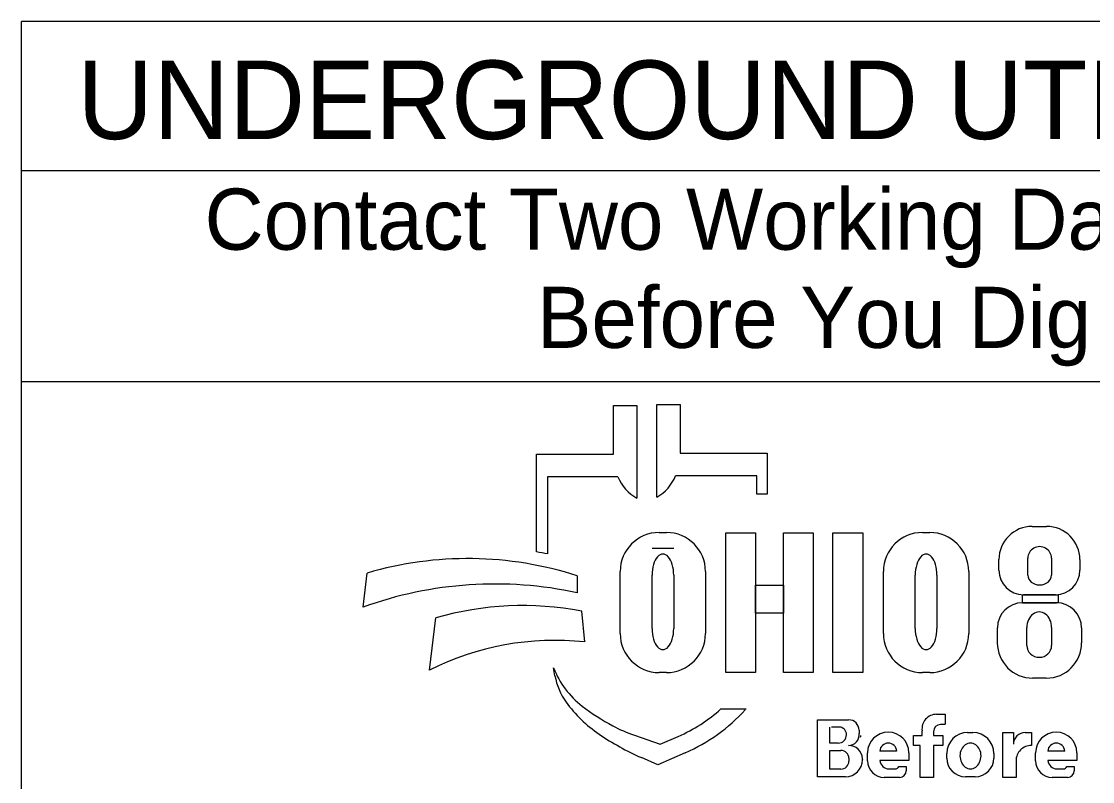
# Model space of a CAD drawing. Extents: x 0 to 2329303, y 0 to 694397.
# Drawn here: x 3 to 5.454, y 3.565 to 5.307 of the extents above; entities that cross this region are included whole.
import ezdxf

# ---------------------------------------------------------------- set-up
doc = ezdxf.new("R2010")
doc.units = 0
doc.layers.add('SH_Data', color=7, linetype='Continuous')

msp = doc.modelspace()

# ---------------------------------------------------------------- linework, layer by layer
at = {"layer": 'SH_Data'}
for p, q in [((3, 2.97), (3, 5.3075)), ((7.25, 5.3075), (3, 5.3075)), ((3, 4.9659), (7.25, 4.9659)), ((3, 4.4825), (7.25, 4.4825)), ((4.356, 4.3155), (4.356, 4.427)), ((4.356, 4.427), (4.4097, 4.427)), ((4.4097, 4.427), (4.4097, 4.2149)), ((4.4553, 4.2172), (4.4553, 4.4293)), ((4.4553, 4.4293), (4.509, 4.4293)), ((4.509, 4.4293), (4.509, 4.3178)), ((4.1801, 4.0916), (4.1801, 4.3155)), ((4.1801, 4.3155), (4.356, 4.3155)), ((4.509, 4.3178), (4.7082, 4.3178)), ((4.7082, 4.3178), (4.7082, 4.224)), ((4.2053, 4.264), (4.2053, 4.0872)), ((4.3664, 4.264), (4.2053, 4.264)), ((4.6849, 4.2664), (4.4986, 4.2664)), ((4.6849, 4.224), (4.6849, 4.2664)), ((4.7082, 4.224), (4.6849, 4.224)), ((5.3156, 4.1503), (5.3483, 4.1503)), ((4.461, 4.1363), (4.4776, 4.1363)), ((5.0641, 4.1363), (5.0806, 4.1363)), ((4.4943, 4.0993), (4.4445, 4.0993)), ((5.2393, 4.0497), (5.2393, 4.074)), ((5.3054, 4.0383), (5.3054, 4.0776)), ((5.3596, 4.0776), (5.3596, 4.0383)), ((5.4246, 4.074), (5.4246, 4.0497)), ((3.7827, 3.9653), (3.7921, 4.0434)), ((4.2734, 4.0369), (4.2734, 3.9981)), ((4.3716, 3.9048), (4.3716, 4.0468)), ((4.4445, 3.9162), (4.4445, 4.0385)), ((4.4943, 4.0385), (4.4943, 3.9162)), ((4.567, 4.0468), (4.567, 3.9048)), ((4.9746, 3.9048), (4.9746, 4.0468)), ((5.0475, 3.9162), (5.0475, 4.0385)), ((5.0973, 4.0385), (5.0973, 3.9162)), ((5.1701, 4.0468), (5.1701, 3.9048)), ((5.2935, 3.9754), (5.3708, 3.9754)), ((5.3686, 3.9937), (5.2953, 3.9937)), ((4.2833, 3.9563), (4.2896, 3.8854)), ((3.9345, 3.8208), (3.9492, 3.9409)), ((5.2356, 3.8835), (5.2356, 3.9175)), ((5.3031, 3.8775), (5.3031, 3.9184)), ((5.3599, 3.9184), (5.3599, 3.8775)), ((5.4287, 3.9175), (5.4287, 3.8835)), ((4.2222, 3.8079), (4.2192, 3.8258)), ((4.4776, 3.8153), (4.461, 3.8153)), ((5.0806, 3.8153), (5.0641, 3.8153)), ((5.3477, 3.8025), (5.3165, 3.8025)), ((4.6025, 3.732), (4.6599, 3.732)), ((4.8238, 3.5762), (4.8238, 3.707)), ((4.8238, 3.707), (4.895, 3.707)), ((5.0964, 3.7197), (5.1158, 3.7197)), ((5.1158, 3.7197), (5.1158, 3.6968)), ((4.8518, 3.6535), (4.8518, 3.6904)), ((4.877, 3.6904), (4.8557, 3.6904)), ((4.9187, 3.6832), (4.9187, 3.6753)), ((5.0631, 3.6714), (5.0631, 3.6818)), ((5.1158, 3.6963), (5.1057, 3.6963)), ((4.4041, 3.6716), (4.4635, 3.6511)), ((4.4635, 3.6511), (4.5045, 3.6689)), ((5.0438, 3.6484), (5.0438, 3.6714)), ((5.0438, 3.6714), (5.0631, 3.6714)), ((5.0892, 3.6798), (5.0892, 3.6714)), ((5.0892, 3.6714), (5.1108, 3.6714)), ((5.1108, 3.6714), (5.1108, 3.6484)), ((5.1676, 3.6779), (5.1797, 3.6779)), ((5.2479, 3.575), (5.2479, 3.6777)), ((5.2479, 3.6777), (5.2724, 3.6777)), ((5.2724, 3.6777), (5.2724, 3.6508)), ((5.2997, 3.6777), (5.3135, 3.6777)), ((5.3135, 3.6777), (5.3135, 3.6481)), ((4.5208, 3.6316), (4.4575, 3.6041)), ((4.8712, 3.6535), (4.8518, 3.6535)), ((4.8518, 3.5941), (4.8518, 3.6369)), ((4.8518, 3.6369), (4.8773, 3.6369)), ((5.0049, 3.6354), (4.9664, 3.6354)), ((5.0587, 3.6484), (5.0438, 3.6484)), ((5.0587, 3.575), (5.0587, 3.6484)), ((5.1108, 3.6484), (5.0892, 3.6484)), ((5.0892, 3.6484), (5.0892, 3.575)), ((5.3899, 3.6354), (5.3513, 3.6354)), ((4.4575, 3.6041), (4.4201, 3.6205)), ((4.8954, 3.6188), (4.8954, 3.6124)), ((4.9268, 3.6159), (4.9268, 3.6156)), ((4.9384, 3.613), (4.9384, 3.6314)), ((5.0329, 3.6137), (4.9665, 3.6137)), ((5.0329, 3.6314), (5.0329, 3.6137)), ((5.1198, 3.6193), (5.1198, 3.6301)), ((5.2276, 3.6301), (5.2276, 3.6193)), ((5.2784, 3.6132), (5.2784, 3.575)), ((5.3233, 3.613), (5.3233, 3.6314)), ((5.4178, 3.6137), (5.3514, 3.6137)), ((5.4178, 3.6314), (5.4178, 3.6137)), ((4.8771, 3.5941), (4.8518, 3.5941)), ((4.9874, 3.5945), (5.0015, 3.5945)), ((5.0101, 3.6001), (5.0269, 3.6001)), ((5.0269, 3.6001), (5.0269, 3.5903)), ((5.3723, 3.5945), (5.3864, 3.5945)), ((5.395, 3.6001), (5.4119, 3.6001)), ((5.4119, 3.6001), (5.4119, 3.5903)), ((4.8875, 3.5762), (4.8238, 3.5762)), ((5.0117, 3.575), (4.9763, 3.575)), ((5.0892, 3.575), (5.0587, 3.575)), ((5.1848, 3.5766), (5.1626, 3.5766)), ((5.2784, 3.575), (5.2479, 3.575)), ((5.3966, 3.575), (5.3612, 3.575))]:
    msp.add_line(p, q, dxfattribs=at)
for points in [[(4.6135, 4.1352), (4.6814, 4.1352), (4.6814, 3.8153), (4.6135, 3.8153)], [(4.7456, 4.1352), (4.8136, 4.1352), (4.8136, 3.8153), (4.7456, 3.8153)], [(4.8589, 4.1352), (4.9277, 4.1352), (4.9277, 3.8153), (4.8589, 3.8153)], [(4.6814, 4.0154), (4.7456, 4.0154), (4.7456, 3.9514), (4.6814, 3.9514)], [(5.2931, 3.9937), (5.3748, 3.9937), (5.3748, 3.9752), (5.2931, 3.9752)]]:
    msp.add_lwpolyline(points, close=True, dxfattribs=at)
for centre, radius, start, end in [((4.4578, 4.3008), 0.0985, 201.9296, 240.7469), ((4.4072, 4.3031), 0.0985, 299.2531, 338.0704), ((5.3156, 4.074), 0.0763, 90, 180), ((5.3483, 4.074), 0.0763, 0, 90), ((4.461, 4.0468), 0.0895, 90, 180), ((4.4776, 4.0468), 0.0895, 0, 90), ((5.0641, 4.0468), 0.0895, 90, 180), ((5.0806, 4.0468), 0.0895, 0, 90), ((4.0222, 3.2573), 0.8191, 72.1402, 106.3144), ((4.0519, 3.2826), 0.8191, 79.2074, 81.0007), ((5.2953, 4.0497), 0.056, 180, 270), ((5.3686, 4.0497), 0.056, 270, 0), ((4.0852, 3.1262), 0.8919, 77.8238, 109.8274), ((5.2935, 3.9175), 0.0579, 90, 180), ((5.3708, 3.9175), 0.0579, 0, 90), ((4.1492, 3.2365), 0.7322, 79.44, 105.8467), ((4.461, 3.9048), 0.0895, 180, 270), ((4.4776, 3.9048), 0.0895, 270, 0), ((5.0641, 3.9048), 0.0895, 180, 270), ((5.0806, 3.9048), 0.0895, 270, 0), ((4.2212, 3.2533), 0.6357, 83.8248, 116.8021), ((5.3165, 3.8835), 0.081, 180, 270), ((5.3477, 3.8835), 0.081, 270, 0), ((4.4066, 3.8979), 0.2008, 201.0457, 232.5314), ((4.3635, 3.832), 0.1433, 189.6817, 216.0884), ((4.4972, 3.9294), 0.3088, 216.0884, 235.7167), ((4.5991, 4.1491), 0.5173, 232.5314, 241.794), ((4.3611, 3.9994), 0.3602, 293.4582, 312.0712), ((4.3611, 3.9994), 0.401, 293.4582, 317.8286), ((4.895, 3.6832), 0.0238, 0, 90), ((5.0964, 3.6862), 0.0335, 90, 187.5187), ((4.5139, 3.9903), 0.3371, 241.794, 250.9821), ((4.873, 3.6735), 0.0169, 357.8325, 90), ((5.1057, 3.6798), 0.0165, 90, 180), ((4.6637, 4.1736), 0.6044, 235.7167, 246.2325), ((4.8712, 3.6722), 0.0187, 270, 2.0582), ((4.8946, 3.6725), 0.0243, 270, 6.6529), ((4.9052, 3.671), 0.0175, 347.4023, 0), ((4.9856, 3.6314), 0.0473, 0, 180), ((5.1676, 3.6301), 0.0478, 90, 180), ((5.1797, 3.6301), 0.0478, 0, 90), ((5.2993, 3.6508), 0.0269, 89.2449, 180), ((5.3705, 3.6314), 0.0473, 0, 180), ((4.8773, 3.6188), 0.0181, 0, 90), ((4.8947, 3.6161), 0.0321, 4.0748, 90), ((4.9857, 3.6344), 0.0193, 2.9632, 177.0368), ((5.3133, 3.6132), 0.0349, 89.6033, 180), ((5.3706, 3.6344), 0.0193, 2.9632, 177.0368), ((4.8771, 3.6124), 0.0184, 270, 0), ((4.8875, 3.6156), 0.0393, 270, 0), ((4.8938, 3.6159), 0.033, 0, 11.7502), ((4.9763, 3.613), 0.038, 180, 270), ((4.9874, 3.6155), 0.021, 184.827, 270), ((5.1626, 3.6193), 0.0428, 180, 270), ((5.1848, 3.6193), 0.0428, 270, 0), ((5.3612, 3.613), 0.038, 180, 270), ((5.3723, 3.6155), 0.021, 184.827, 270), ((5.0015, 3.6039), 0.00938, 270, 335.9979), ((5.0117, 3.5903), 0.0152, 270, 0), ((5.3864, 3.6039), 0.00938, 270, 335.9979), ((5.3966, 3.5903), 0.0152, 270, 0)]:
    msp.add_arc(centre, radius, start, end, dxfattribs=at)
for centre, major_axis, ratio, start_param, end_param in [((5.3325, 4.0776), (0.0271, 0), 0.969373, 0, 3.141593), ((4.4694, 4.0385), (0, 0.0484), 0.514403, 4.712389, 7.853982), ((5.0724, 4.0385), (0, 0.0484), 0.514403, 4.712389, 7.853982), ((5.3325, 4.0383), (0.0271, 0), 0.818453, 3.141593, 6.283185), ((5.3315, 3.9184), (0, 0.0358), 0.794529, 4.712389, 7.853982), ((4.4694, 3.9162), (0, 0.0484), 0.514403, 1.570796, 4.712389), ((5.0724, 3.9162), (0, 0.0484), 0.514403, 1.570796, 4.712389), ((5.3315, 3.8775), (0.0284, 0), 0.959837, 3.141593, 6.283185), ((5.1741, 3.6247), (0, 0.029), 0.832186, 4.712389, 7.853982), ((5.1741, 3.6247), (0, 0.0302), 0.797287, 1.570796, 4.712389)]:
    msp.add_ellipse(centre, major_axis=major_axis, ratio=ratio, start_param=start_param, end_param=end_param, dxfattribs=at)

# ---------------------------------------------------------------- texts
for s, height, p in [('UNDERGROUND UTILITIES', 0.18, (3.1282, 5.0378)), ('Contact Two Working Days', 0.14, (3.4196, 4.7843)), ('Before You Dig', 0.14, (4.1808, 4.5593))]:
    msp.add_text(s, height=height, dxfattribs=at).set_placement(p)

doc.saveas('drawing.dxf')
